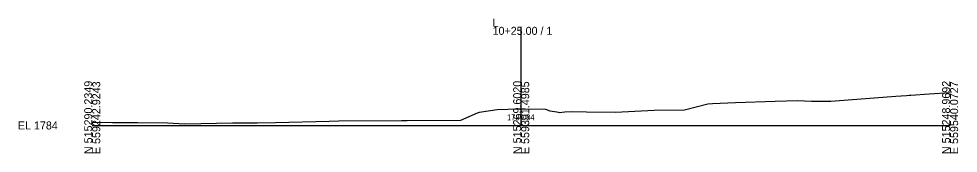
# Model space of a CAD drawing. Extents: x -26 to 1303, y -10 to 9545.
# Drawn here: x -25.7 to 302.8, y 490.3 to 537.3 of the extents above; entities that cross this region are included whole.
import ezdxf

# ---------------------------------------------------------------- set-up
doc = ezdxf.new("R2010")
doc.units = 0
for name, color, linetype in [('Exist Cross Section Cell', 7, 'Continuous'), ('Exist XS Center Line Elevation Label', 7, 'Continuous'), ('Exist XS Ground Line', 7, 'Continuous')]:
    doc.layers.add(name, color=color, linetype=linetype)

msp = doc.modelspace()

# ---------------------------------------------------------------- linework, layer by layer
at = {"layer": 'Exist Cross Section Cell'}
for p, q in [((150, 500), (150, 534.46)), ((0, 500), (150, 500)), ((150, 500), (300, 500))]:
    msp.add_line(p, q, dxfattribs=at)
at = {"layer": 'Exist XS Ground Line'}
for p, q in [((258.24, 508.45), (281.02, 510.25)), ((281.02, 510.25), (284.72, 510.48)), ((284.72, 510.48), (285.63, 510.56)), ((285.63, 510.56), (286.22, 510.6)), ((286.22, 510.6), (292.66, 511.02)), ((292.66, 511.02), (300, 511.49)), ((207.06, 505.43), (215.29, 507.55)), ((215.29, 507.55), (216.93, 507.72)), ((216.93, 507.72), (224.99, 508.05)), ((224.99, 508.05), (238.81, 508.5)), ((238.81, 508.5), (246.62, 508.71)), ((246.62, 508.71), (251.55, 508.52)), ((251.55, 508.52), (254.35, 508.46)), ((254.35, 508.46), (255.93, 508.51)), ((255.93, 508.51), (258.24, 508.45)), ((128.94, 501.83), (134.78, 504.45)), ((134.78, 504.45), (135.43, 504.68)), ((135.43, 504.68), (136.17, 504.78)), ((136.17, 504.78), (141.66, 505.54)), ((141.66, 505.54), (149.01, 505.81)), ((149.01, 505.81), (150.21, 505.85)), ((150.21, 505.85), (151.42, 505.82)), ((151.42, 505.82), (158.56, 505.64)), ((158.56, 505.64), (160.08, 505.14)), ((160.08, 505.14), (162.52, 504.74)), ((162.52, 504.74), (162.91, 504.63)), ((162.91, 504.63), (163.32, 504.54)), ((163.32, 504.54), (165.28, 504.75)), ((165.28, 504.75), (167.94, 504.92)), ((167.94, 504.92), (172.81, 504.8)), ((172.81, 504.8), (182.99, 504.63)), ((182.99, 504.63), (196.56, 505.3)), ((196.56, 505.3), (207.06, 505.43)), ((0, 501.19), (7.08, 501.06)), ((7.08, 501.06), (15.85, 501.07)), ((15.85, 501.07), (26.36, 500.89)), ((26.36, 500.89), (32.43, 500.52)), ((32.43, 500.52), (49.03, 500.97)), ((49.03, 500.97), (57.62, 500.91)), ((57.62, 500.91), (64.07, 501.05)), ((64.07, 501.05), (82.86, 501.5)), ((82.86, 501.5), (86.29, 501.59)), ((86.29, 501.59), (108.13, 501.74)), ((108.13, 501.74), (109.18, 501.73)), ((109.18, 501.73), (110.16, 501.72)), ((110.16, 501.72), (128.94, 501.83))]:
    msp.add_line(p, q, dxfattribs=at)

# ---------------------------------------------------------------- texts
at = {"layer": 'Exist Cross Section Cell'}
for s, p in [('L', (140, 534.46)), ('10+25.00 / 1', (140, 531.66)), ('EL 1784', (-26, 498.6))]:
    msp.add_text(s, height=2.8, dxfattribs=at).set_placement(p)
for s, p in [('N 515290.2349', (0, 490)), ('E 559242.9243', (2.8, 490)), ('N 515269.6020', (150, 490)), ('E 559391.4985', (152.8, 490)), ('N 515248.9692', (300, 490)), ('E 559540.0727', (302.8, 490))]:
    msp.add_text(s, height=2.8, rotation=90, dxfattribs=at).set_placement(p)
at = {"layer": 'Exist XS Center Line Elevation Label'}
msp.add_text('1789.84', height=2, dxfattribs=at).set_placement((145.02, 501.84))

doc.saveas('drawing.dxf')
